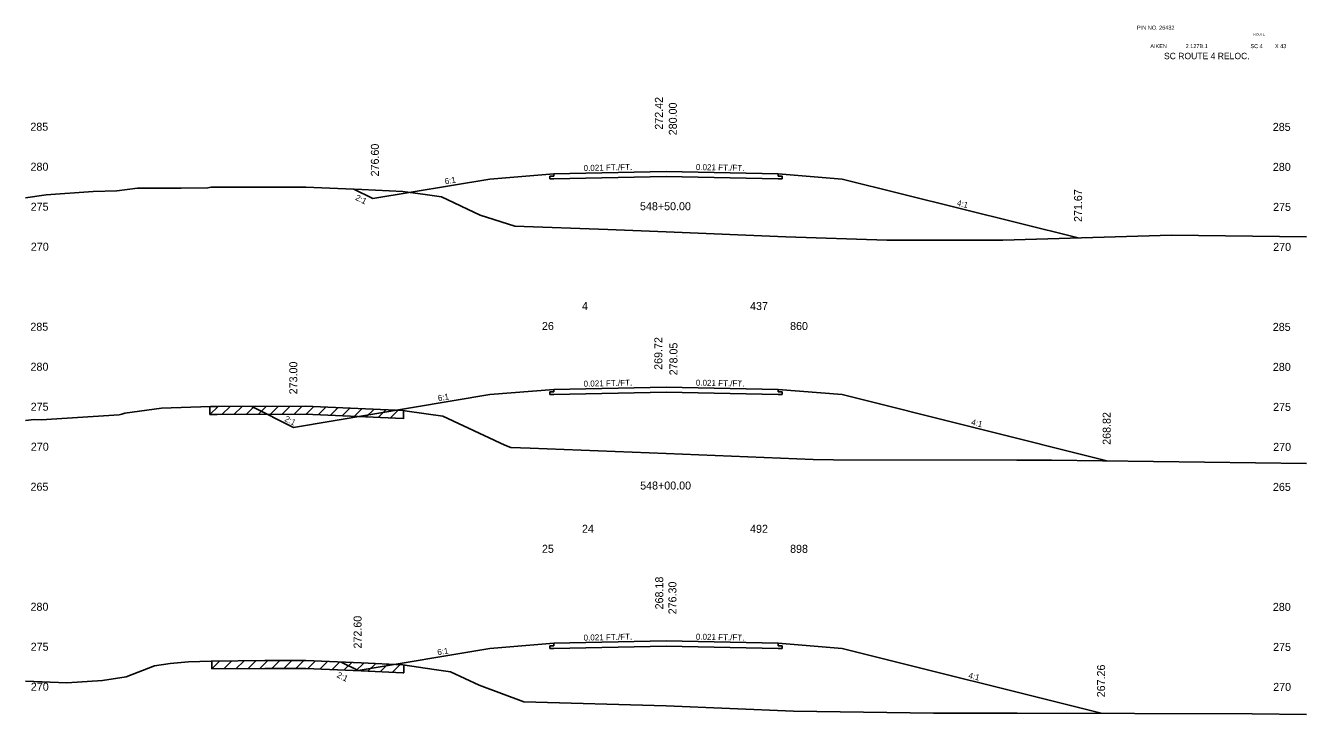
# Model space of a CAD drawing. Extents: x 2967 to 4323, y -3677 to -817.
# Drawn here: x 3555.3 to 3715.3, y -1707.7 to -1621.6 of the extents above; entities that cross this region are included whole.
import ezdxf

# ---------------------------------------------------------------- set-up
doc = ezdxf.new("R2010")
doc.units = 0
for name, color, linetype in [('Level 1', 7, 'Continuous'), ('Level 10', 7, 'Continuous'), ('Level 11', 7, 'Continuous'), ('Level 12', 7, 'Continuous'), ('Level 20', 7, 'Continuous'), ('Level 3', 7, 'Continuous'), ('Level 32', 7, 'Continuous'), ('Level 33', 7, 'Continuous'), ('Level 59', 7, 'Continuous'), ('Level 6', 7, 'Continuous'), ('Level 60', 7, 'Continuous'), ('Level 61', 7, 'Continuous'), ('Level 7', 7, 'Continuous')]:
    doc.layers.add(name, color=color, linetype=linetype)

msp = doc.modelspace()

# ---------------------------------------------------------------- linework, layer by layer
at = {"layer": 'Level 11'}
for p, q in [((3621.35, -1640.43), (3620.85, -1640.44)), ((3620.85, -1640.44), (3620.85, -1640.78)), ((3620.85, -1640.78), (3621.35, -1640.77)), ((3621.35, -1640.13), (3621.35, -1640.43)), ((3649.35, -1640.43), (3649.35, -1640.13)), ((3649.85, -1640.44), (3649.35, -1640.43)), ((3649.35, -1640.77), (3649.85, -1640.78)), ((3649.85, -1640.78), (3649.85, -1640.44)), ((3621.35, -1667.09), (3621.35, -1667.39)), ((3649.35, -1667.39), (3649.35, -1667.09)), ((3621.35, -1667.39), (3620.85, -1667.4)), ((3620.85, -1667.4), (3620.85, -1667.74)), ((3620.85, -1667.74), (3621.35, -1667.73)), ((3649.85, -1667.4), (3649.35, -1667.39)), ((3649.35, -1667.73), (3649.85, -1667.74)), ((3649.85, -1667.74), (3649.85, -1667.4)), ((3621.35, -1699.13), (3620.85, -1699.14)), ((3620.85, -1699.14), (3620.85, -1699.48)), ((3621.35, -1698.83), (3621.35, -1699.13)), ((3649.35, -1699.13), (3649.35, -1698.83)), ((3649.85, -1699.14), (3649.35, -1699.13)), ((3649.85, -1699.48), (3649.85, -1699.14)), ((3620.85, -1699.48), (3621.35, -1699.47)), ((3649.35, -1699.47), (3649.85, -1699.48))]:
    msp.add_line(p, q, dxfattribs=at)
at = {"layer": 'Level 12'}
for p, q in [((3635.35, -1640.48), (3621.35, -1640.77)), ((3649.35, -1640.77), (3635.35, -1640.48)), ((3635.35, -1667.44), (3621.35, -1667.73)), ((3649.35, -1667.73), (3635.35, -1667.44)), ((3635.35, -1699.18), (3621.35, -1699.47)), ((3649.35, -1699.47), (3635.35, -1699.18))]:
    msp.add_line(p, q, dxfattribs=at)
at = {"layer": 'Level 59'}
for p, q in [((3621.35, -1640.13), (3635.35, -1639.84)), ((3635.35, -1639.84), (3649.35, -1640.13)), ((3621.35, -1667.09), (3635.35, -1666.8)), ((3635.35, -1666.8), (3649.35, -1667.09)), ((3621.35, -1698.83), (3635.35, -1698.54)), ((3635.35, -1698.54), (3649.35, -1698.83))]:
    msp.add_line(p, q, dxfattribs=at)
at = {"layer": 'Level 6'}
for p, q in [((3613.35, -1640.8), (3621.35, -1640.13)), ((3649.35, -1640.13), (3657.35, -1640.8)), ((3613.35, -1667.75), (3621.35, -1667.09)), ((3649.35, -1667.09), (3657.35, -1667.75)), ((3613.35, -1699.5), (3621.35, -1698.83)), ((3649.35, -1698.83), (3657.35, -1699.5))]:
    msp.add_line(p, q, dxfattribs=at)
at = {"layer": 'Level 60'}
for p, q in [((3555.35, -1643.15), (3557.91, -1642.76)), ((3557.91, -1642.76), (3563.77, -1642.37)), ((3563.77, -1642.37), (3566.75, -1642.29)), ((3566.75, -1642.29), (3569.34, -1641.94)), ((3569.34, -1641.94), (3574.78, -1641.94)), ((3574.78, -1641.94), (3578.1, -1641.91)), ((3578.1, -1641.91), (3578.53, -1641.82)), ((3578.53, -1641.82), (3585.31, -1641.8)), ((3585.31, -1641.8), (3590.35, -1641.8)), ((3590.35, -1641.8), (3597.34, -1642.11)), ((3597.34, -1642.11), (3602.49, -1642.35)), ((3602.49, -1642.35), (3605.26, -1642.74)), ((3605.26, -1642.74), (3607.3, -1643.03)), ((3607.3, -1643.03), (3612.15, -1645.31)), ((3612.15, -1645.31), (3616.45, -1646.71)), ((3616.45, -1646.71), (3628.09, -1647.12)), ((3628.09, -1647.12), (3635.35, -1647.42)), ((3635.35, -1647.42), (3650.33, -1648.04)), ((3677.43, -1648.46), (3698.51, -1647.81)), ((3698.51, -1647.81), (3715.35, -1648.04)), ((3650.33, -1648.04), (3662.95, -1648.45)), ((3662.95, -1648.45), (3677.43, -1648.46)), ((3557.31, -1670.9), (3567.02, -1670.26)), ((3567.02, -1670.26), (3567.36, -1670.2)), ((3567.36, -1670.2), (3567.76, -1670.05)), ((3567.76, -1670.05), (3572.31, -1669.44)), ((3572.31, -1669.44), (3578.46, -1669.24)), ((3578.46, -1669.24), (3579.28, -1669.24)), ((3579.28, -1669.24), (3590.35, -1669.21)), ((3590.35, -1669.21), (3591.22, -1669.24)), ((3591.22, -1669.24), (3602.51, -1669.75)), ((3602.51, -1669.75), (3603.03, -1669.83)), ((3603.03, -1669.83), (3607.48, -1670.45)), ((3555.35, -1670.99), (3556.42, -1670.87)), ((3556.42, -1670.87), (3557.31, -1670.9)), ((3607.48, -1670.45), (3615.21, -1674.07)), ((3615.21, -1674.07), (3615.97, -1674.36)), ((3615.97, -1674.36), (3618.38, -1674.43)), ((3618.38, -1674.43), (3635.35, -1675.12)), ((3635.35, -1675.12), (3653.75, -1675.87)), ((3653.75, -1675.87), (3656.26, -1675.91)), ((3656.26, -1675.91), (3679.17, -1675.92)), ((3679.17, -1675.92), (3683.52, -1675.93)), ((3683.52, -1675.93), (3715.35, -1676.34)), ((3567.89, -1703.01), (3571.43, -1701.63)), ((3571.43, -1701.63), (3573.41, -1701.36)), ((3573.41, -1701.36), (3575.68, -1701.14)), ((3575.68, -1701.14), (3578.52, -1701.05)), ((3578.52, -1701.05), (3585.25, -1701)), ((3585.25, -1701), (3590.35, -1700.98)), ((3590.35, -1700.98), (3597.26, -1701.29)), ((3597.26, -1701.29), (3602.47, -1701.52)), ((3602.47, -1701.52), (3606.39, -1702.1)), ((3606.39, -1702.1), (3608.44, -1702.39)), ((3608.44, -1702.39), (3611.99, -1704.05)), ((3555.35, -1703.55), (3560.49, -1703.76)), ((3560.49, -1703.76), (3564.97, -1703.46)), ((3564.97, -1703.46), (3567.89, -1703.01)), ((3611.99, -1704.05), (3617.58, -1706.16)), ((3617.58, -1706.16), (3635.35, -1706.66)), ((3635.35, -1706.66), (3651.29, -1707.32)), ((3651.29, -1707.32), (3668.77, -1707.56)), ((3668.77, -1707.56), (3679.2, -1707.56)), ((3679.2, -1707.56), (3708.56, -1707.63)), ((3708.56, -1707.63), (3715.35, -1707.72))]:
    msp.add_line(p, q, dxfattribs=at)
at = {"layer": 'Level 61'}
for p, q in [((3579.39, -1669.24), (3578.38, -1670.24)), ((3578.38, -1669.24), (3578.38, -1670.24)), ((3578.38, -1670.24), (3578.46, -1670.24)), ((3578.46, -1670.24), (3579.28, -1670.24)), ((3579.28, -1670.24), (3590.35, -1670.21)), ((3580.89, -1669.23), (3579.88, -1670.23)), ((3582.39, -1669.23), (3581.38, -1670.23)), ((3583.89, -1669.22), (3582.88, -1670.23)), ((3585.39, -1669.22), (3584.38, -1670.22)), ((3586.89, -1669.22), (3585.88, -1670.22)), ((3588.39, -1669.21), (3587.38, -1670.21)), ((3589.89, -1669.21), (3588.88, -1670.21)), ((3590.35, -1670.21), (3591.22, -1670.24)), ((3591.34, -1669.25), (3590.38, -1670.21)), ((3591.22, -1670.24), (3602.51, -1670.75)), ((3592.84, -1669.32), (3591.88, -1670.27)), ((3594.34, -1669.38), (3593.38, -1670.34)), ((3595.84, -1669.45), (3594.88, -1670.41)), ((3597.34, -1669.52), (3596.38, -1670.48)), ((3598.84, -1669.59), (3597.88, -1670.54)), ((3600.34, -1669.65), (3599.38, -1670.61)), ((3601.84, -1669.72), (3600.88, -1670.68)), ((3602.55, -1670.76), (3602.55, -1669.76)), ((3602.51, -1670.75), (3602.55, -1670.76)), ((3579.63, -1701.04), (3578.62, -1702.04)), ((3578.62, -1701.04), (3578.62, -1702.04)), ((3578.62, -1702.04), (3585.25, -1702)), ((3581.13, -1701.03), (3580.12, -1702.03)), ((3582.63, -1701.01), (3581.62, -1702.02)), ((3584.13, -1701), (3583.12, -1702.01)), ((3585.62, -1700.99), (3584.62, -1702)), ((3585.25, -1702), (3590.35, -1701.98)), ((3587.12, -1700.99), (3586.12, -1701.99)), ((3588.62, -1700.99), (3587.62, -1701.99)), ((3590.12, -1700.98), (3589.12, -1701.98)), ((3590.35, -1701.98), (3597.26, -1702.29)), ((3591.58, -1701.04), (3590.62, -1701.99)), ((3593.08, -1701.1), (3592.12, -1702.06)), ((3594.58, -1701.17), (3593.62, -1702.13)), ((3596.08, -1701.24), (3595.12, -1702.19)), ((3597.58, -1701.3), (3596.62, -1702.26)), ((3597.26, -1702.29), (3602.47, -1702.52)), ((3599.08, -1701.37), (3598.12, -1702.33)), ((3600.58, -1701.44), (3599.62, -1702.4)), ((3602.08, -1701.51), (3601.12, -1702.46)), ((3602.61, -1702.54), (3602.61, -1701.54)), ((3602.47, -1702.52), (3602.61, -1702.54))]:
    msp.add_line(p, q, dxfattribs=at)
at = {"layer": 'Level 7'}
for p, q in [((3598.71, -1643.24), (3613.35, -1640.8)), ((3657.35, -1640.8), (3686.83, -1648.17)), ((3598.71, -1643.24), (3596.37, -1642.07)), ((3588.83, -1671.84), (3613.35, -1667.75)), ((3657.35, -1667.75), (3690.4, -1676.02)), ((3588.83, -1671.84), (3583.6, -1669.22)), ((3596.9, -1702.24), (3613.35, -1699.5)), ((3657.35, -1699.5), (3689.7, -1707.58)), ((3596.9, -1702.24), (3594.78, -1701.18))]:
    msp.add_line(p, q, dxfattribs=at)

# ---------------------------------------------------------------- texts
at = {"layer": 'Level 1'}
for s, p in [('4', (3624.85, -1657.17)), ('437', (3645.85, -1657.17)), ('26', (3619.85, -1659.67)), ('860', (3650.85, -1659.67)), ('24', (3624.85, -1685.02)), ('492', (3645.85, -1685.02)), ('25', (3619.85, -1687.52)), ('898', (3650.85, -1687.52))]:
    msp.add_text(s, height=1, dxfattribs=at).set_placement(p)
at = {"layer": 'Level 10'}
for s, p in [('272.42', (3634.96, -1634.63)), ('269.72', (3634.89, -1664.65)), ('268.18', (3635, -1694.59))]:
    msp.add_text(s, height=1, rotation=90, dxfattribs=at).set_placement(p)
for s, p in [('548+50.00', (3632.1, -1644.7)), ('548+00.00', (3632.12, -1679.61))]:
    msp.add_text(s, height=1, dxfattribs=at).set_placement(p)
at = {"layer": 'Level 20'}
for s, height, p in [('PIN NO. 26432', 0.5, (3694.19, -1622.13)), ('AIKEN', 0.5, (3695.85, -1624.44)), (' 2.127B.1', 0.5, (3700.07, -1624.44)), ('SC 4', 0.5, (3708.36, -1624.44)), ('ROUTE', 0.3, (3708.73, -1622.87)), ('X 43', 0.5, (3711.42, -1624.44)), ('SC ROUTE 4 RELOC.', 0.8, (3697.56, -1625.82))]:
    msp.add_text(s, height=height, dxfattribs=at).set_placement(p)
at = {"layer": 'Level 3'}
for s, p in [(' 285', (3555.57, -1634.76)), (' 285', (3710.78, -1634.78)), (' 280', (3555.59, -1639.76)), (' 280', (3710.79, -1639.78)), (' 275', (3555.61, -1644.76)), (' 275', (3710.82, -1644.78)), (' 270', (3555.63, -1649.76)), (' 270', (3710.83, -1649.78)), (' 285', (3555.57, -1659.76)), (' 285', (3710.78, -1659.78)), (' 280', (3555.59, -1664.76)), (' 280', (3710.79, -1664.78)), (' 275', (3555.61, -1669.76)), (' 275', (3710.82, -1669.78)), (' 270', (3555.63, -1674.76)), (' 270', (3710.83, -1674.78)), (' 265', (3555.59, -1679.76)), (' 265', (3710.8, -1679.78)), (' 280', (3555.59, -1694.76)), (' 280', (3710.79, -1694.78)), (' 275', (3555.61, -1699.76)), (' 275', (3710.82, -1699.78)), (' 270', (3555.63, -1704.76)), (' 270', (3710.83, -1704.78))]:
    msp.add_text(s, height=1, dxfattribs=at).set_placement(p)
at = {"layer": 'Level 32'}
for s, rotation, p in [('0.021 FT./FT.', 1.1916, (3625.06, -1639.8)), ('0.021 FT./FT.', 358.8084, (3639.07, -1639.67)), ('6:1', 9.4623, (3607.77, -1641.47)), ('2:1', 333.435, (3596.47, -1643.36)), ('4:1', 345.9638, (3671.63, -1644.11)), ('0.021 FT./FT.', 1.1916, (3625.06, -1666.76)), ('0.021 FT./FT.', 358.8084, (3639.07, -1666.62)), ('6:1', 9.4623, (3606.91, -1668.57)), ('2:1', 333.435, (3587.62, -1671.02)), ('4:1', 345.9638, (3673.42, -1671.51)), ('0.021 FT./FT.', 1.1916, (3625.06, -1698.5)), ('0.021 FT./FT.', 358.8084, (3639.07, -1698.37)), ('6:1', 9.4623, (3606.84, -1700.33)), ('2:1', 333.435, (3594.15, -1703.03)), ('4:1', 345.9638, (3673.07, -1703.17))]:
    msp.add_text(s, height=0.75, rotation=rotation, dxfattribs=at).set_placement(p)
at = {"layer": 'Level 33'}
for s, p in [('276.60', (3599.48, -1640.47)), ('271.67', (3687.33, -1646.17)), ('273.00', (3589.29, -1667.71)), ('268.82', (3690.9, -1674.02)), ('272.60', (3597.32, -1699.48)), ('267.26', (3690.2, -1705.58))]:
    msp.add_text(s, height=1, rotation=90, dxfattribs=at).set_placement(p)
at = {"layer": 'Level 59'}
for s, p in [(' 280.00', (3636.7, -1635.7)), (' 278.05', (3636.78, -1665.71)), (' 276.30', (3636.65, -1695.58))]:
    msp.add_text(s, height=1, rotation=90, dxfattribs=at).set_placement(p)

doc.saveas('drawing.dxf')
